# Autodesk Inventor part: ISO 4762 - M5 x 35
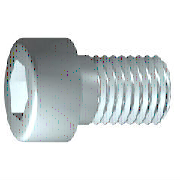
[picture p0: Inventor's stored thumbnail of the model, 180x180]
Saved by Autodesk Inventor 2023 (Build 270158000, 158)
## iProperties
IsCustomPart: 0
Created: 2021-02
Part Number: ISO 4762 - M5 x 35
Material: Stainless Steel, 440C
Description: Hexagon Socket Head Cap Screw
Document SubType Name: Modeling
Standard: ISO 4762
Designer: larsb
Standard Revision: Fourth edition 2004-03-01
Standards Organization: ISO
Language: en-US
Size Designation: M5 x 35
Categories: <MemberInstance><Categories><Category DisplayName="Fasteners" InternalName="e4da775c-781d-43d5-af7c-5136215cf5a6" Mnemonic="FSTN"><Category DisplayName="Bolts"
Density: 7.75 g/cm^3
Appearance: Semi-Polished
Author: larsb
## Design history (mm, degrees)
sketch "Sketch1"
  geometry: L1 (-1.167, 0)-(35, 0); L2 (35, 0)-(35, 2.5); L3 (35, 2.5)-(13, 2.5); L4 (13, 2.5)-(12.509, 2.5); L5 (12.509, 2.5)-(0, 2.5); L6 (0, 2.5)-(0, 4.25); L7 (0, 4.25)-(-5, 4.25); L8 (-5, 4.25)-(-5, 2.309); L9 (-5, 2.309)-(-2.5, 2.309); L10 (-2.5, 2.309)-(-1.167, 0); L11 (-13, 0)-(43, 0) reference; L12 (0, -0.85)-(0, 5.1) reference; L13 (13, 2.5)-(0, 2.5)
  constraints: 22 end point, 6 parallel, 2 collinear, 2 perpendicular, 1 horizontal, 1 point on line
  dimensions: "d1" = 22 distance from line of L3.end L2 (= GEL); "d2" = 0.49086 distance of L4.end L3.end (computed from GAL); "d3" = 5 distance between parallel lines of L8 L6 (= KOH); "d4" = 2.5 distance of L8.end L9.end (= INTI); "d5" = 60 deg angle of L10 L1; "d6" = 5 diameter of L3 L1 (= GD); "d7" = 5 diameter of L5 L1 (= BDM); "d8" = 4.6188 diameter of L9 L1 (= 1.1547 x SW); "d9" = 8.5 diameter of L7 L1 (= KOD); "d26" = 35 distance between parallel lines of L12 L2 (= NLG)
revolve "Body" sketch "Sketch1" stored, may be unused: angle "d10" = 90 deg
sketch "Sketch2"
  geometry: L1 (0, -5.95)-(0, 5.95) reference; L2 (-5.95, 0)-(5.95, 0) reference; L3 (2.309, 0)-(1.155, -2); L4 (1.155, -2)-(-1.155, -2); L5 (-1.155, -2)-(-2.309, 0); L6 (-2.309, 0)-(-1.155, 2); L7 (-1.155, 2)-(1.155, 2); L8 (1.155, 2)-(2.309, 0); 2 further points
  constraints: 12 end point, 1 coincident, 1 horizontal alignment, 1 point on line, 12 other
extrude "Slot" join sketch "Sketch2" stored distance "d11" = 10; taper "d12" = 0 deg
workplane "Work Plane1"
fillet "Fillet2" dims "d30" = 0.1 (= R)
body "Solid1"
fillet "Fillet1" dims "d17" = 0.5 (= RR)
feature "Thread" dims "d13" = 22 (= GEL), "d14" = 0
chamfer "Chamfer1" distance "d15" = 0.49076 (= -0.5 x SPD + 0.5 x GD); stored, may be unused: second distance "d16" = 0.49076 (= GUL), angle "d27" = 45 deg
other parameters: "GD" = 5 [user parameter; used in 2 equation terms], "NLG" = 35 [user parameter; used in 1 equation term], "GEL" = 22 [user parameter; used in 2 equation terms], "KOD" = 8.5 [user parameter; used in 1 equation term], "KOH" = 5 [user parameter; used in 1 equation term], "INTI" = 2.5 [user parameter; used in 1 equation term], "GAL" = 0.49076 (= 0.61345 x PTC) [user parameter; used in 1 equation term], "GUL" = 0.49076 (= 0.61345 x PTC) [user parameter; used in 1 equation term], "BDM" = 5 (= NND) [user parameter; used in 1 equation term], "SW" = 4 [user parameter; used in 2 equation terms], "RR" = 0.5 [user parameter; used in 1 equation term], "SPD" = 4.01848 (= NND - 1.2269 x PTC) [user parameter; used in 1 equation term], "d19" = 0, "d28" = 0, "d29" = 0, "R" = 0.1 [user parameter; used in 1 equation term], "TOA" = 30 deg [user parameter], "GD1" = 4.01848 (= THREADDIA - 1.2269 x PTC) [user parameter], "THREADDIA" = 5 [user parameter; used in 1 equation term], "FAWI" = 45 deg [user parameter], "TPU" = 12.5 (computed from PTC) [user parameter], "PTC" = 0.8 [user parameter; used in 5 equation terms], "NND" = 5 [user parameter; used in 2 equation terms], "E0" = 4.62 (= 1.155 x SW) [user parameter]
